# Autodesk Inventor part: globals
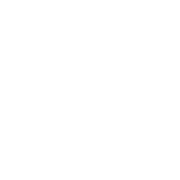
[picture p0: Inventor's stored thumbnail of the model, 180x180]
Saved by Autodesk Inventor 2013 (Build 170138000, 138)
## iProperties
Created: 2013-11
Part Number: globals
Material: Generic
Document SubType Name: Modeling
Designer: Jonas
Density: 1 g/cm^3
theta: 3,00 deg
frame_height: 710,000 mm
clearance_top: 400,000 mm
clearance_side: 250,000 mm
side_bracket_padding_top: 100,000 mm
sprocket_N: 22,000 ul
sprocket_wall_clearance: 1,000 mm
ball_diameter: 2,450 mm
ball_distance: 0,760 mm
frame_thickness: 21,500 mm
pi: 3,142 ul
outer_bearing_ring_d: 60,000 mm
pen_hole_d: 25,000 mm
layer_height: 0,270 mm
v_wheel_outer_d: 12,000 mm
Author: Jonas
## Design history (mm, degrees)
other parameters: "theta" = 3 deg [user parameter], "frame_height" = 710 [user parameter], "clearance_top" = 400 [user parameter], "clearance_side" = 250 [user parameter], "side_bracket_padding_top" = 100 [user parameter], "sprocket_N" = 22 [user parameter], "sprocket_wall_clearance" = 1 [user parameter], "ball_diameter" = 2.45 [user parameter; used in 1 equation term], "ball_distance" = 0.76 (computed from ball_diameter) [user parameter], "frame_thickness" = 21.5 [user parameter], "pi" = 3.14159 [user parameter], "outer_bearing_ring_d" = 60 [user parameter], "pen_hole_d" = 25 [user parameter], "layer_height" = 0.27 [user parameter], "v_wheel_outer_d" = 12 [user parameter]
